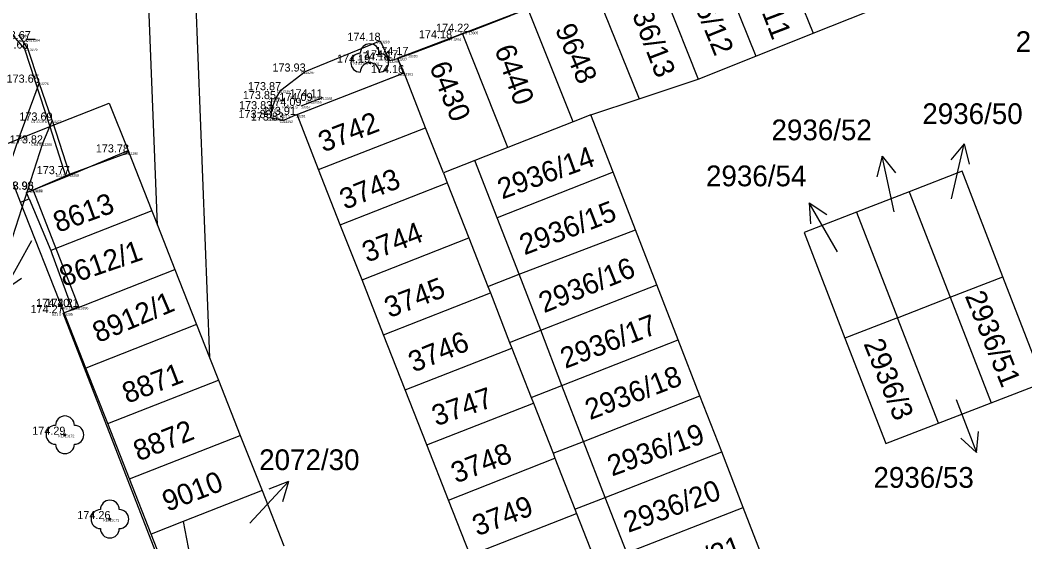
# Model space of a CAD drawing. Extents: x -566117 to -565580, y -1202428 to -1201938.
# Drawn here: x -565682.2 to -565628.9, y -1202226.6 to -1202198.9 of the extents above; entities that cross this region are included whole.
import ezdxf

# ---------------------------------------------------------------- set-up
doc = ezdxf.new("R2010")
doc.units = 0
for name, color, linetype in [('(Construction)', 7, 'Continuous'), ('1029', 7, 'Continuous'), ('_0', 7, 'Continuous'), ('Bod', 7, 'Continuous'), ('Implicitní', 7, 'Continuous'), ('Kanalizace', 7, 'Continuous'), ('Katastr', 7, 'Continuous'), ('Kod', 7, 'Continuous'), ('Vrstva 59', 7, 'Continuous'), ('Vrstva 61', 7, 'Continuous'), ('Výška', 7, 'Continuous'), ('ZELEŇ', 7, 'Continuous'), ('Zpevněné plohy', 7, 'Continuous'), ('Číslo', 7, 'Continuous')]:
    doc.layers.add(name, color=color, linetype=linetype)

# ---------------------------------------------------------------- blocks, each defined once
blk = doc.blocks.new('1029$2')
at = {"layer": 'Katastr'}
for p, q in [((0, 3.001), (-0.501, 2)), ((0, 0), (0, 3.001)), ((0, 3.001), (0.501, 2))]:
    blk.add_line(p, q, dxfattribs=at)
blk = doc.blocks.new('A$C69D74C1E')
at = {"layer": 'Katastr'}
for p, q in [((390.63, -92.3), (392.79, -148.4)), ((390.03, -141.37), (388.15, -93.11)), ((422.33, -125.08), (424.77, -131.2)), ((419.29, -126.3), (421.73, -132.41)), ((416.25, -127.51), (418.69, -133.63)), ((413.08, -128.57), (415.56, -134.68)), ((406.19, -131.21), (409.66, -129.89)), ((412.05, -135.89), (409.66, -129.89)), ((424.77, -131.2), (427.68, -130.04)), ((408.6, -137.25), (406.19, -131.21)), ((421.73, -132.41), (424.77, -131.2)), ((418.69, -133.63), (421.73, -132.41)), ((404.24, -136.21), (403.1, -133.29)), ((415.56, -134.68), (418.69, -133.63)), ((412.99, -135.52), (415.56, -134.68)), ((384.32, -136.15), (387.48, -134.91)), ((387.48, -134.91), (388.47, -137.42)), ((412.99, -135.52), (412.05, -135.89)), ((414.17, -138.57), (412.99, -135.52)), ((381.62, -137.22), (384.32, -136.15)), ((398.57, -138.43), (404.24, -136.21)), ((405.18, -138.6), (404.24, -136.21)), ((412.05, -135.89), (408.6, -137.25)), ((382.77, -140.15), (381.62, -137.22)), ((408.6, -137.25), (406.85, -137.94)), ((399.72, -141.35), (398.57, -138.43)), ((406.85, -137.94), (405.18, -138.6)), ((405.18, -138.6), (405.39, -139.13)), ((415.36, -141.62), (414.17, -138.57)), ((399.72, -141.35), (405.39, -139.13)), ((405.39, -139.13), (406.53, -142.05)), ((383.24, -139.97), (384.38, -142.72)), ((429.87, -139.6), (427.08, -140.68)), ((429.87, -139.6), (432.04, -145.2)), ((389.73, -140.61), (384.38, -142.72)), ((389.73, -140.61), (389.81, -140.8)), ((389.81, -140.8), (390.03, -141.37)), ((409.19, -143.98), (408.03, -140.99)), ((427.08, -140.68), (429.24, -146.28)), ((390.03, -141.37), (390.95, -143.72)), ((400.87, -144.27), (399.72, -141.35)), ((409.19, -143.98), (415.36, -141.62)), ((416.49, -144.53), (415.36, -141.62)), ((400.87, -144.27), (406.53, -142.05)), ((406.53, -142.05), (407.53, -144.62)), ((385.53, -145.86), (390.95, -143.72)), ((390.95, -143.72), (392.1, -146.65)), ((402.01, -147.19), (400.87, -144.27)), ((407.53, -144.62), (409.19, -143.98)), ((410.34, -146.95), (409.19, -143.98)), ((432.04, -145.2), (434.83, -144.12)), ((407.53, -144.62), (407.67, -144.97)), ((410.34, -146.95), (416.49, -144.53)), ((417.62, -147.45), (416.49, -144.53)), ((402.01, -147.19), (407.67, -144.97)), ((407.67, -144.97), (408.69, -147.6)), ((429.24, -146.28), (432.04, -145.2)), ((432.04, -145.2), (434.2, -150.8)), ((385.53, -145.86), (385.09, -146.03)), ((386.24, -148.96), (385.09, -146.03)), ((429.24, -146.28), (426.45, -147.36)), ((431.41, -151.88), (429.24, -146.28)), ((392.1, -146.65), (386.24, -148.96)), ((392.1, -146.65), (392.79, -148.4)), ((408.69, -147.6), (410.34, -146.95)), ((411.46, -149.87), (410.34, -146.95)), ((403.16, -150.11), (402.01, -147.19)), ((411.46, -149.87), (417.62, -147.45)), ((418.77, -150.43), (417.62, -147.45)), ((403.16, -150.11), (408.81, -147.9)), ((408.69, -147.6), (408.81, -147.9)), ((408.81, -147.9), (409.83, -150.51)), ((392.79, -148.4), (393.26, -149.59)), ((387.4, -151.9), (386.24, -148.96)), ((387.4, -151.9), (393.26, -149.59)), ((393.26, -149.59), (394.41, -152.52)), ((404.31, -153.03), (403.16, -150.11)), ((409.83, -150.51), (411.46, -149.87)), ((412.61, -152.84), (411.46, -149.87)), ((409.83, -150.51), (409.95, -150.81)), ((412.61, -152.84), (418.77, -150.43)), ((419.93, -153.4), (418.77, -150.43)), ((404.31, -153.03), (409.95, -150.81)), ((409.95, -150.81), (410.99, -153.47)), ((431.41, -151.88), (434.2, -150.8)), ((388.55, -154.83), (387.4, -151.9)), ((388.55, -154.83), (394.41, -152.52)), ((394.41, -152.52), (395.57, -155.45)), ((405.45, -155.95), (404.31, -153.03)), ((410.99, -153.47), (412.61, -152.84)), ((413.76, -155.81), (412.61, -152.84)), ((405.45, -155.95), (411.09, -153.73)), ((410.99, -153.47), (411.09, -153.73)), ((411.09, -153.73), (412.15, -156.44)), ((413.76, -155.81), (419.93, -153.4)), ((421.07, -156.34), (419.93, -153.4)), ((389.7, -157.76), (388.55, -154.83)), ((395.57, -155.45), (391.39, -157.09)), ((395.57, -155.45), (396.72, -158.38)), ((406.6, -158.87), (405.45, -155.95)), ((412.15, -156.44), (413.76, -155.81)), ((414.9, -158.75), (413.76, -155.81)), ((412.15, -156.44), (412.24, -156.66)), ((414.9, -158.75), (421.07, -156.34)), ((422.2, -159.27), (421.07, -156.34)), ((406.6, -158.87), (412.24, -156.66)), ((412.24, -156.66), (413.3, -159.37)), ((391.39, -157.09), (389.7, -157.76)), ((391.39, -157.09), (391.99, -160.24)), ((390.86, -160.69), (389.7, -157.76))]:
    blk.add_line(p, q, dxfattribs=at)
for points in [[(364.58, -135.63), (366.2, -135.31), (368.15, -135.68), (369.92, -136.92), (370.92, -138.61), (373.12, -145.57), (377.96, -143.83), (375.18, -135.67), (375.3, -133.89), (376.11, -132.39), (377.74, -131.31), (380.41, -130.61), (381.97, -130.88), (382.99, -132.03)], [(403.1, -133.29), (402.75, -132.52), (406.19, -131.21)], [(382.99, -132.03), (384.32, -136.15), (385.18, -138.82)], [(398.57, -138.43), (397.43, -135.51), (403.1, -133.29)], [(385.18, -138.82), (388.47, -137.42), (388.66, -137.87), (389.73, -140.61)], [(414.17, -138.57), (408.03, -140.99), (406.85, -137.94)], [(383.24, -139.97), (383.1, -139.65), (385.18, -138.82)], [(434.83, -144.12), (432.67, -138.52), (429.87, -139.6)], [(385.09, -146.03), (382.77, -140.15), (383.24, -139.97)], [(427.08, -140.68), (424.29, -141.76), (426.45, -147.36)], [(384.38, -142.72), (384.43, -142.88), (385.53, -145.86)], [(434.2, -150.8), (437, -149.72), (434.83, -144.12)], [(426.45, -147.36), (428.62, -152.96), (431.41, -151.88)]]:
    blk.add_lwpolyline(points, dxfattribs=at)
at = {"layer": '1029'}
for p, rotation in [((432.11, -139.98), -13.000000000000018), ((429.06, -140.66), 11.999999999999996), ((426.07, -142.79), 29.999999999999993), ((383.36, -142.2), 151), ((432.35, -150.62), -159), ((394.93, -157.17), -42.999999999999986)]:
    blk.add_blockref('1029$2', p, dxfattribs=dict(at, rotation=rotation))
at = {"layer": 'Katastr'}
for s, rotation, p in [('2936/11', 291, (420.722, -126.649)), ('2936/12', 292, (417.59, -127.543)), ('2936/13', 291, (414.582, -128.679)), ('9648', 293, (411.08, -130.97)), ('6440', 290, (407.875, -132.035)), ('6430', 292, (404.42, -132.953)), ('3742', 21, (398.819, -137.528)), ('2936/14', 20, (408.295, -140.015)), ('3743', 22, (399.963, -140.57)), ('8613', 20, (384.755, -141.785)), ('2936/15', 21, (409.479, -142.978)), ('3744', 21, (401.139, -143.368)), ('8612/1', 19, (385.07, -144.649)), ('2936/16', 22, (410.513, -146.05)), ('3745', 21, (402.319, -146.308)), ('8912/1', 23, (386.887, -147.632)), ('2936/51', 292, (432.8, -145.123)), ('2936/17', 21, (411.639, -148.998)), ('3746', 22, (403.603, -149.2)), ('2936/3', 292, (427.43, -147.653)), ('8871', 21, (388.429, -150.848)), ('2936/18', 21, (412.949, -151.718)), ('3747', 19, (404.801, -152.043)), ('8872', 22, (389.033, -153.91)), ('2936/19', 20, (414.115, -154.705)), ('3748', 21, (405.849, -155.078)), ('9010', 21, (390.549, -156.578)), ('2936/20', 20, (414.975, -157.695)), ('3749', 21, (406.979, -157.878)), ('2936/21', 21, (416.159, -160.738))]:
    blk.add_text(s, height=1.1, rotation=rotation, dxfattribs=at).set_placement(p)
for s, p in [('2936/48', (435.507, -132.193)), ('2936/50', (430.56, -136.013)), ('2936/52', (422.567, -136.873)), ('2936/54', (419.097, -139.313)), ('2072/30', (395.42, -154.363)), ('2936/53', (427.97, -155.3))]:
    blk.add_text(s, height=1.1, dxfattribs=at).set_placement(p)
blk = doc.blocks.new('STROM')
at = {"layer": 'ZELEŇ'}
blk.add_circle((0, 0), 0.05, dxfattribs=at)
for centre, start, end in [((0, 0.5), 0, 180), ((-0.5, 0), 90, 270), ((0, -0.5), 0, 180), ((0.5, 0), 270, 90)]:
    blk.add_arc(centre, 0.5, start, end, dxfattribs=at)
blk = doc.blocks.new('3.13')
at = {"layer": 'ZELEŇ'}
blk.add_circle((0, 0), 0.1, dxfattribs=at)
for centre, start, end in [((0, 1), 0, 180), ((-1, 0), 90, 270), ((1, 0), 270, 90), ((0, -1), 180, 0)]:
    blk.add_arc(centre, 1, start, end, dxfattribs=at)
blk = doc.blocks.new('VP')
at = {"layer": 'Kanalizace'}
blk.add_line((-0.25, 0), (0.25, 0), dxfattribs=at)
blk = doc.blocks.new('POINT_DISPLAY')
at = {"layer": 'Implicitní'}
blk.add_line((0, 0), (0, 0), dxfattribs=at)

msp = doc.modelspace()

# ---------------------------------------------------------------- linework, layer by layer
at = {"layer": '(Construction)'}
for p, q in [((-565662.17, -1202200.97), (-565655.28, -1202198.35)), ((-565661.86, -1202201.75), (-565662.17, -1202200.97)), ((-565667.55, -1202203.97), (-565661.86, -1202201.75)), ((-565679.56, -1202207.11), (-565676.43, -1202205.96)), ((-565681.48, -1202207.94), (-565679.56, -1202207.11)), ((-565679.06, -1202214.15), (-565681.48, -1202207.94)), ((-565679.89, -1202214.48), (-565679.06, -1202214.15))]:
    msp.add_line(p, q, dxfattribs=at)
msp.add_lwpolyline([(-565664.66, -1202249.19), (-565666.21, -1202249.82), (-565679.89, -1202214.48)], dxfattribs=at)
at = {"layer": '_0'}
for p, q in [((-565658.4, -1202199.56), (-565656.17, -1202198.7)), ((-565661.62, -1202200.79), (-565659.31, -1202199.91)), ((-565667.29, -1202203.49), (-565666.13, -1202203.04))]:
    msp.add_line(p, q, dxfattribs=at)
at = {"layer": 'Zpevněné plohy'}
for p, q in [((-565681.76, -1202200.45), (-565682.25, -1202199.72)), ((-565667.07, -1202201.67), (-565663.1, -1202200.04)), ((-565663.1, -1202200.04), (-565662.61, -1202201.08)), ((-565681.16, -1202202.26), (-565681.76, -1202200.45)), ((-565662.61, -1202201.08), (-565662.17, -1202200.97)), ((-565668.37, -1202202.66), (-565667.07, -1202201.67)), ((-565680.48, -1202204.27), (-565681.16, -1202202.26)), ((-565668.64, -1202203.13), (-565668.37, -1202202.66)), ((-565668.84, -1202203.67), (-565668.64, -1202203.13)), ((-565668.87, -1202204.14), (-565668.84, -1202203.67)), ((-565680.48, -1202204.27), (-565679.56, -1202207.11)), ((-565668.22, -1202204.27), (-565668.87, -1202204.14)), ((-565667.55, -1202203.97), (-565668.22, -1202204.27))]:
    msp.add_line(p, q, dxfattribs=at)
for points in [[(-565681.16, -1202202.26), (-565682.24, -1202205.18), (-565684.92, -1202212.93)], [(-565680.48, -1202204.27), (-565680.99, -1202205.48), (-565683.22, -1202212.42), (-565682.89, -1202213.52)]]:
    msp.add_lwpolyline(points, dxfattribs=at)

# ---------------------------------------------------------------- block references
at = {"layer": 'Bod'}
for p in [(-565681.63, -1202199.95), (-565663.1, -1202200.04), (-565659.31, -1202199.91), (-565658.4, -1202199.56), (-565681.76, -1202200.45), (-565662.61, -1202201.08), (-565662.17, -1202200.97), (-565661.62, -1202200.79), (-565663.65, -1202201.2), (-565667.07, -1202201.67), (-565661.86, -1202201.75), (-565681.16, -1202202.26), (-565668.37, -1202202.66), (-565668.64, -1202203.13), (-565666.7, -1202203.23), (-565666.13, -1202203.04), (-565668.84, -1202203.67), (-565667.29, -1202203.49), (-565680.48, -1202204.27), (-565668.87, -1202204.14), (-565668.22, -1202204.27), (-565667.55, -1202203.97), (-565680.99, -1202205.48), (-565676.43, -1202205.96), (-565679.56, -1202207.11), (-565681.49, -1202207.93), (-565681.48, -1202207.94), (-565679.61, -1202214.15), (-565679.06, -1202214.15), (-565679.89, -1202214.48), (-565679.8, -1202220.93), (-565677.42, -1202225.4)]:
    msp.add_blockref('POINT_DISPLAY', p, dxfattribs=at)
at = {"layer": 'Implicitní'}
msp.add_blockref('A$C69D74C1E', (-566064.93, -1202068.44), dxfattribs=at)
at = {"layer": 'Vrstva 59', "xscale": 0.5, "yscale": 0.5}
for p in [(-565679.8, -1202220.93), (-565677.42, -1202225.4)]:
    msp.add_blockref('3.13', p, dxfattribs=at)
at = {"layer": 'Vrstva 61'}
msp.add_blockref('VP', (-565681.63, -1202199.95), dxfattribs=at)
at = {"layer": 'ZELEŇ'}
msp.add_blockref('STROM', (-565663.65, -1202201.2), dxfattribs=at)

# ---------------------------------------------------------------- texts
at = {"layer": 'Kod'}
for s, p in [('UV', (-565681.847, -1202200.08)), ('C2', (-565663.305, -1202200.17)), ('V1', (-565659.472, -1202200.04)), ('V1 S', (-565658.872, -1202199.69)), ('C1', (-565681.922, -1202200.58)), ('BZ1 C2', (-565662.895, -1202201.1)), ('C2', (-565662.815, -1202201.21)), ('V1 S', (-565662.092, -1202200.92)), ('STR-R20', (-565664.517, -1202201.33)), ('C2', (-565667.275, -1202201.8)), ('BZ1', (-565662.152, -1202201.88)), ('C1', (-565681.322, -1202202.39)), ('C2', (-565668.575, -1202202.79)), ('C2', (-565668.845, -1202203.26)), ('SKE', (-565667.042, -1202203.36)), ('PRISE1', (-565666.812, -1202203.17)), ('C2', (-565669.045, -1202203.8)), ('PRISE1 S', (-565668.282, -1202203.62)), ('C1 S C9 S', (-565681.602, -1202204.4)), ('C2', (-565669.075, -1202204.27)), ('BZ1 S C2 S', (-565668.802, -1202204.1)), ('C2', (-565668.425, -1202204.4)), ('CH4 S', (-565681.592, -1202205.61)), ('BZ1', (-565676.722, -1202206.09)), ('BZ1 C9', (-565680.285, -1202207.24)), ('BZ1', (-565681.772, -1202208.07)), ('BZ', (-565681.701, -1202208.06)), ('PRIS', (-565680.082, -1202214.28)), ('BZ1', (-565679.352, -1202214.28)), ('BZ1 S', (-565680.492, -1202214.61)), ('KER', (-565680.141, -1202221.06)), ('KER', (-565677.761, -1202225.53))]:
    msp.add_text(s, height=0.13, dxfattribs=at).set_placement(p)
at = {"layer": 'Výška'}
for s, p in [('173.67 ', (-565683.367, -1202199.95)), ('174.18 ', (-565661.047, -1202199.91)), ('174.22 ', (-565660.137, -1202199.56)), ('173.66 ', (-565683.488, -1202200.45)), ('174.18 ', (-565664.837, -1202200.04)), ('174.17 ', (-565663.907, -1202200.97)), ('174.17 ', (-565663.357, -1202200.79)), ('174.19 ', (-565665.387, -1202201.2)), ('174.16 ', (-565664.338, -1202201.08)), ('173.93 ', (-565668.807, -1202201.67)), ('174.16 ', (-565663.588, -1202201.75)), ('173.65 ', (-565682.897, -1202202.26)), ('173.85 ', (-565670.377, -1202203.13)), ('173.87 ', (-565670.107, -1202202.66)), ('174.11 ', (-565667.903, -1202203.04)), ('173.83 ', (-565670.577, -1202203.67)), ('174.09 ', (-565669.027, -1202203.49)), ('174.09 ', (-565668.437, -1202203.23)), ('173.83 ', (-565670.607, -1202204.14)), ('173.91 ', (-565669.323, -1202203.97)), ('173.69 ', (-565682.217, -1202204.27)), ('173.83 ', (-565669.957, -1202204.27)), ('173.82 ', (-565682.727, -1202205.48)), ('173.78 ', (-565678.167, -1202205.96)), ('173.77 ', (-565681.297, -1202207.11)), ('173.98 ', (-565683.227, -1202207.93)), ('173.96 ', (-565683.208, -1202207.94)), ('174.20 ', (-565681.33, -1202214.15)), ('174.21 ', (-565680.833, -1202214.15)), ('174.27 ', (-565681.627, -1202214.48)), ('174.29 ', (-565681.537, -1202220.93)), ('174.26 ', (-565679.148, -1202225.4))]:
    msp.add_text(s, height=0.43, dxfattribs=at).set_placement(p)
at = {"layer": 'Číslo'}
for s, p in [('13280', (-565682.25, -1202199.85)), ('13284', (-565681.63, -1202200.08)), ('13298', (-565663.1, -1202200.17)), ('13304', (-565659.31, -1202200.04)), ('13305', (-565658.4, -1202199.69)), ('13279', (-565681.76, -1202200.58)), ('13299', (-565662.61, -1202201.21)), ('13302', (-565662.17, -1202201.1)), ('13303', (-565661.62, -1202200.92)), ('13300', (-565663.65, -1202201.33)), ('13297', (-565667.07, -1202201.8)), ('13301', (-565661.86, -1202201.88)), ('13278', (-565681.16, -1202202.39)), ('13296', (-565668.37, -1202202.79)), ('13295', (-565668.64, -1202203.26)), ('13356', (-565666.7, -1202203.36)), ('13358', (-565666.13, -1202203.17)), ('13294', (-565668.84, -1202203.8)), ('13357', (-565667.29, -1202203.62)), ('13277', (-565680.48, -1202204.4)), ('13293', (-565668.87, -1202204.27)), ('13292', (-565668.22, -1202204.4)), ('13291', (-565667.55, -1202204.1)), ('12289', (-565682.24, -1202205.31)), ('12288', (-565680.99, -1202205.61)), ('13290', (-565676.43, -1202206.09)), ('13289', (-565679.56, -1202207.24)), ('13177', (-565681.49, -1202208.06)), ('13288', (-565681.48, -1202208.07)), ('13287', (-565679.61, -1202214.28)), ('13286', (-565679.06, -1202214.28)), ('13285', (-565679.89, -1202214.61)), ('13172', (-565679.8, -1202221.06)), ('13171', (-565677.42, -1202225.53))]:
    msp.add_text(s, height=0.13, dxfattribs=at).set_placement(p)

doc.saveas('drawing.dxf')
